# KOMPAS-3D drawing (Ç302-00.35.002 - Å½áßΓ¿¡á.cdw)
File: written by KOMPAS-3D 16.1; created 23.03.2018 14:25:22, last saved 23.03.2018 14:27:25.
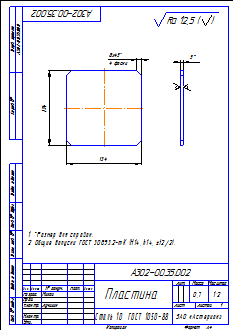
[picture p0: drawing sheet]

Sheet 1: A4, portrait

Title block, sheet 1: name: Пластина; designation: А302-00.35.002; material: Сталь 10  ГОСТ 1050-88; mass: 0,7; scale: 1:2; sheets: 1; organisation: ЗАО «Астерион»; sheet format: A4; stored path: \\192.168.87.28\Konstructor_doc\Мембранные насосы\Мембранный электропривод\А302-00.00.000 - ASTRA-302 (МЭ200)\Чертежи\А302-00.35.002 - Пластина.cdw; drawn by: Милов; technical control: Лучихин

Views: Вид 1, Спереди, Проекционный вид 2
Referenced files in Z:\Мембранные насосы\Мембранный электропривод\А302-00.00.000 - ASTRA-302 (МЭ200)\3Д\: А302-00.35.002 - Пластина.m3d
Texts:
  *Размер для справок.
  Общие допуски ГОСТ 30893.2-mK (H14, h14,  t2/2).
  Ra 12,5
  Ra 12,5 ( )
Dimensions and other numbers on the sheet: 134; 8; 4 фаски; 5; 1:2; 1; 0,7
